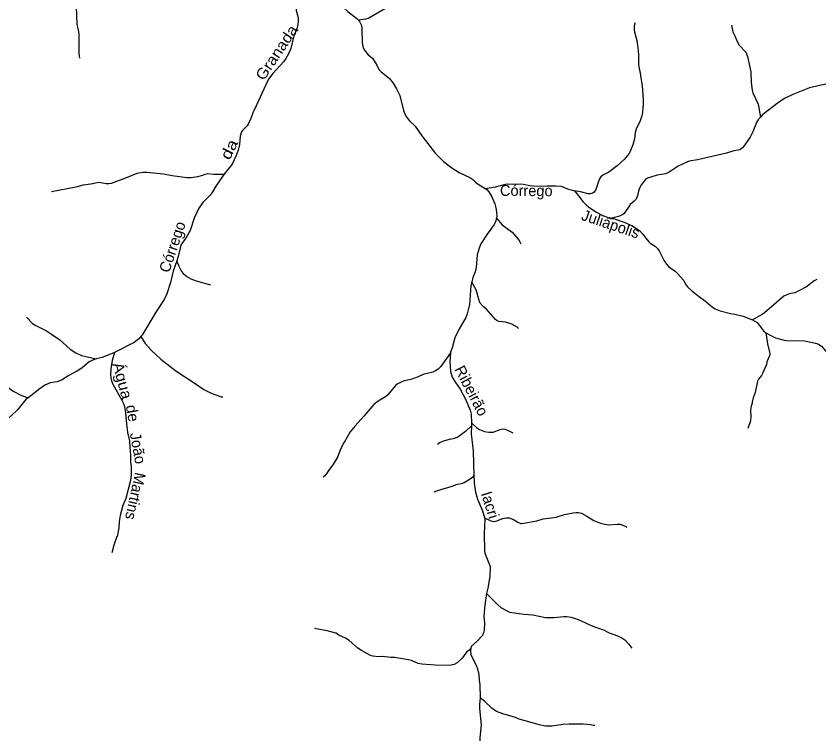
# Model space of a CAD drawing. Extents: x 551.6 to 577.6, y 7567 to 7594.7.
# Drawn here: x 561.8 to 569.17, y 7573.14 to 7579.74 of the extents above; entities that cross this region are included whole.
import ezdxf
from ezdxf.enums import TextEntityAlignment as Align

# ---------------------------------------------------------------- set-up
doc = ezdxf.new("R2010")
doc.units = 0
doc.header["$LTSCALE"] = 0.04
doc.layers.add('61', color=7, linetype='Continuous')
doc.layers.add('7', color=7, linetype='Continuous', lineweight=25)

msp = doc.modelspace()

# ---------------------------------------------------------------- linework, layer by layer
at = {"layer": '7'}
for points in [[(562.302, 7580.2565), (562.2867, 7580.209), (562.2851, 7580.1704), (562.2883, 7580.1511), (562.2883, 7580.077), (562.2931, 7580.032), (562.3068, 7579.9756), (562.3301, 7579.9048), (562.3494, 7579.8227), (562.3543, 7579.6585), (562.368, 7579.6102), (562.372, 7579.57), (562.3736, 7579.3913), (562.3784, 7579.3503)], [(564.2614, 7580.1319), (564.2761, 7580.0754), (564.2906, 7580.0368), (564.3156, 7579.9957), (564.3486, 7579.9563), (564.3598, 7579.9306), (564.3647, 7579.8919), (564.3647, 7579.8275), (564.3687, 7579.7889), (564.3856, 7579.7229), (564.3872, 7579.6972), (564.3824, 7579.6585), (564.3735, 7579.6199), (564.3462, 7579.5555), (564.3188, 7579.4396), (564.2971, 7579.3881), (564.2729, 7579.3455), (564.2504, 7579.3149), (564.1522, 7579.2094), (564.1144, 7579.1579), (564.0878, 7579.1064), (564.0009, 7578.9117)], [(564.7399, 7579.9589), (564.7518, 7579.9467), (564.7791, 7579.8565), (564.7872, 7579.8356), (564.7993, 7579.8195), (564.8403, 7579.7776), (564.9248, 7579.7156), (564.9404, 7579.6981)], [(565.4278, 7579.9949), (565.3715, 7579.9539), (565.332, 7579.916), (565.2693, 7579.8742), (565.1872, 7579.805), (565.0343, 7579.7165), (565.0053, 7579.7084), (564.9404, 7579.6981)], [(564.9404, 7579.6981), (564.9498, 7579.6875), (564.9667, 7579.6489), (564.9715, 7579.6231), (564.9731, 7579.4911), (564.9828, 7579.4461), (564.994, 7579.4219), (565.0294, 7579.3817), (565.0689, 7579.3495), (565.1091, 7579.2867), (565.1228, 7579.2529), (565.1333, 7579.2392), (565.1437, 7579.2271), (565.2234, 7579.1628), (565.2564, 7579.1209), (565.2878, 7579.0694)], [(567.476, 7579.6786), (567.4696, 7579.6376), (567.4704, 7579.6086), (567.4728, 7579.5893), (567.4929, 7579.5121), (567.5034, 7579.4445), (567.5082, 7579.3833), (567.509, 7579.2932), (567.5114, 7579.2706), (567.5259, 7579.2135), (567.5299, 7579.1692), (567.5428, 7579.0968), (567.5525, 7578.9696), (567.5517, 7578.9109), (567.5485, 7578.9036), (567.546, 7578.8505), (567.5404, 7578.8199), (567.5227, 7578.7636), (567.4905, 7578.7073)], [(568.3645, 7579.6529), (568.3758, 7579.5925), (568.3951, 7579.5539), (568.4144, 7579.504), (568.4345, 7579.4686), (568.4941, 7579.4042), (568.5094, 7579.3656), (568.5392, 7579.2239), (568.5432, 7579.1274), (568.552, 7579.0565), (568.5585, 7579.0308), (568.6076, 7578.9278), (568.6289, 7578.8084)], [(569.3866, 7579.1459), (569.3078, 7579.1241), (569.2402, 7579.1145), (569.0776, 7579.0774), (568.9247, 7579.0171), (568.8571, 7578.9817), (568.7943, 7578.943), (568.651, 7578.832), (568.6289, 7578.8084)], [(565.2878, 7579.0694), (565.3192, 7579.0066), (565.353, 7578.8682), (565.3755, 7578.8167), (565.4085, 7578.7749), (565.4608, 7578.7266), (565.522, 7578.6364), (565.6467, 7578.4755), (565.7184, 7578.4014), (565.7972, 7578.3411), (565.864, 7578.2992), (565.9606, 7578.2533), (565.9904, 7578.234), (566.0145, 7578.2099), (566.0387, 7578.1914), (566.1038, 7578.1528)], [(564.0009, 7578.9117), (563.9703, 7578.8473), (563.9518, 7578.7958), (563.9277, 7578.7443), (563.918, 7578.729), (563.8745, 7578.6863), (563.8657, 7578.6735), (563.8528, 7578.6348), (563.848, 7578.5576), (563.8351, 7578.5061), (563.8174, 7578.4546), (563.7788, 7578.3757), (563.7042, 7578.2823)], [(568.6289, 7578.8084), (568.6124, 7578.7909), (568.5931, 7578.7588), (568.5585, 7578.6735), (568.5335, 7578.6252), (568.4764, 7578.5407)], [(567.4905, 7578.7073), (567.48, 7578.667), (567.4728, 7578.6091), (567.4583, 7578.5543), (567.431, 7578.4867), (567.4237, 7578.4755), (567.377, 7578.4183), (567.3127, 7578.3604), (567.2362, 7578.304), (567.1831, 7578.2743), (567.1638, 7578.2598), (567.1509, 7578.2405), (567.142, 7578.2179), (567.1195, 7578.1423), (567.1042, 7578.1205), (567.0865, 7578.1101), (567.0656, 7578.1052), (567.0463, 7578.1052), (566.9787, 7578.1221), (566.9215, 7578.131)], [(568.4764, 7578.5407), (568.4675, 7578.5286), (568.4458, 7578.5109), (568.4241, 7578.5044), (568.3839, 7578.4988), (568.3163, 7578.4787), (568.0523, 7578.4175), (567.975, 7578.4038), (567.9525, 7578.3958), (567.8736, 7578.3588), (567.7899, 7578.304), (567.7593, 7578.2887), (567.6805, 7578.2759), (567.5935, 7578.2477), (567.575, 7578.234), (567.5356, 7578.1882), (567.5163, 7578.1511)], [(563.7042, 7578.2823), (563.6082, 7578.2815), (563.5518, 7578.2871), (563.5293, 7578.2815), (563.5068, 7578.271), (563.4617, 7578.2598), (563.4054, 7578.2517), (563.3651, 7578.2517), (563.2299, 7578.2694), (563.151, 7578.2847), (562.9965, 7578.3), (562.9627, 7578.3), (562.9064, 7578.292), (562.8018, 7578.2469), (562.6698, 7578.2002)], [(563.7042, 7578.2823), (563.6299, 7578.1729), (563.6001, 7578.1214), (563.5768, 7578.0916), (563.5108, 7578.0232), (563.473, 7577.9717), (563.4327, 7577.8815), (563.3941, 7577.7656), (563.3563, 7577.698), (563.3232, 7577.6578), (563.3088, 7577.632), (563.3023, 7577.6063)], [(562.6698, 7578.2002), (562.6472, 7578.1962), (562.6247, 7578.197), (562.5571, 7578.2067), (562.4831, 7578.1922), (562.4139, 7578.1849), (562.3462, 7578.164), (562.1233, 7578.1214)], [(566.1038, 7578.1528), (566.198, 7578.1672), (566.2882, 7578.1938), (566.3107, 7578.197), (566.4008, 7578.193), (566.4234, 7578.1954), (566.4556, 7578.1922), (566.5135, 7578.1793), (566.5779, 7578.1729), (566.668, 7578.1777), (566.7517, 7578.1777), (566.8, 7578.1737), (566.858, 7578.1503), (566.9215, 7578.131)], [(566.1038, 7578.1528), (566.1175, 7578.1447), (566.1368, 7578.123), (566.1642, 7578.0763), (566.19, 7578.0119), (566.1972, 7577.9862)], [(566.9215, 7578.131), (566.9601, 7578.0868), (566.9996, 7578.0344), (567.0286, 7578.0038), (567.0503, 7577.9853), (567.1179, 7577.9395), (567.175, 7577.9073), (567.2539, 7577.8783)], [(567.5163, 7578.1511), (567.505, 7578.1149), (567.5018, 7578.086), (567.4889, 7578.0554), (567.4696, 7578.0352), (567.4334, 7578.0071), (567.431, 7577.999), (567.377, 7577.9242), (567.3561, 7577.9073), (567.3264, 7577.8952), (567.2539, 7577.8783)], [(566.1972, 7577.9862), (566.2044, 7577.9604), (566.2101, 7577.8992), (566.2057, 7577.8815)], [(566.2057, 7577.8815), (566.1972, 7577.8477), (566.1843, 7577.8236), (566.1207, 7577.7335), (566.0636, 7577.6449), (566.0459, 7577.6063), (566.0282, 7577.5451), (566.0201, 7577.426), (566.0105, 7577.3874), (565.9896, 7577.3359), (565.9789, 7577.2913)], [(566.2057, 7577.8815), (566.2568, 7577.8195), (566.3501, 7577.7528), (566.3912, 7577.7061), (566.4129, 7577.6763), (566.4282, 7577.6457)], [(567.2539, 7577.8783), (567.2797, 7577.8759), (567.3795, 7577.8429), (567.4527, 7577.8107), (567.5187, 7577.7664), (567.5436, 7577.7407), (567.5879, 7577.6819), (567.6072, 7577.661), (567.6177, 7577.6513), (567.6636, 7577.624), (567.6853, 7577.6023), (567.6998, 7577.5805), (567.7464, 7577.4888), (567.7674, 7577.4566), (567.7891, 7577.4349), (567.8446, 7577.3938), (567.8672, 7577.3729), (567.9243, 7577.3069), (567.9404, 7577.2731), (567.9581, 7577.249), (568.0008, 7577.2111), (568.0821, 7577.1475), (568.1255, 7577.1194), (568.1674, 7577.0824)], [(563.3023, 7577.6063), (563.2846, 7577.5274), (563.2714, 7577.4883)], [(563.2714, 7577.4883), (563.2396, 7577.3938), (563.2154, 7577.2892), (563.1816, 7577.1862), (563.1575, 7577.1347), (563.0786, 7577.0172), (562.9563, 7576.8112), (562.9409, 7576.7931)], [(563.5832, 7577.2642), (563.452, 7577.3021), (563.4038, 7577.3198), (563.3611, 7577.3447), (563.3385, 7577.364), (563.3136, 7577.3987), (563.2927, 7577.4373), (563.2714, 7577.4883)], [(565.9789, 7577.2913), (565.971, 7577.2586), (565.9574, 7577.0864), (565.9372, 7577.0011), (565.9236, 7576.9673), (565.8616, 7576.8578), (565.8254, 7576.7806)], [(566.4097, 7576.8667), (566.396, 7576.8795), (566.3477, 7576.9061), (566.2897, 7576.9246), (566.227, 7576.9327), (566.2109, 7576.9383), (566.1956, 7576.9504), (566.1127, 7577.0486), (566.0861, 7577.0663), (566.0572, 7577.0993), (566.0467, 7577.1234), (566.0193, 7577.2216), (565.9789, 7577.2913)], [(569.146, 7577.3166), (569.1227, 7577.3037), (569.0502, 7577.2506), (568.981, 7577.2119), (568.9456, 7577.1958), (568.8909, 7577.1846), (568.8426, 7577.1644), (568.6663, 7577.0107), (568.6446, 7576.9954), (568.5552, 7576.9475)], [(561.1141, 7577.092), (561.1294, 7577.0574), (561.1608, 7577.0124), (561.2099, 7576.9222), (561.2348, 7576.8836), (561.296, 7576.8103), (561.3443, 7576.7596), (561.3909, 7576.684), (561.4561, 7576.5914), (561.5511, 7576.4828), (561.6138, 7576.4216), (561.6138, 7576.4176), (561.6646, 7576.3725), (561.77, 7576.2912), (561.8473, 7576.2526), (561.908, 7576.2318)], [(568.1674, 7577.0824), (568.1883, 7577.0638), (568.214, 7577.0477), (568.2583, 7577.0284), (568.3549, 7577.0043), (568.3935, 7576.9995), (568.4692, 7576.9793), (568.5552, 7576.9475)], [(561.894, 7576.9697), (561.9487, 7576.9141), (561.9712, 7576.8989), (562.0774, 7576.8457), (562.1129, 7576.8216), (562.1973, 7576.7636), (562.2923, 7576.6783), (562.3462, 7576.6437), (562.3978, 7576.6196), (562.5332, 7576.5876)], [(568.5552, 7576.9475), (568.5987, 7576.9222), (568.6559, 7576.8466), (568.6786, 7576.8276)], [(562.9409, 7576.7931), (562.9241, 7576.7733), (562.8814, 7576.7395), (562.7003, 7576.6472)], [(562.9409, 7576.7931), (562.982, 7576.7307), (563.0392, 7576.6639), (563.1253, 7576.5858), (563.2621, 7576.4779), (563.4327, 7576.3677), (563.5212, 7576.3057), (563.5808, 7576.2776), (563.6806, 7576.2405), (563.6959, 7576.2381)], [(565.8254, 7576.7806), (565.8004, 7576.6888), (565.7843, 7576.651), (565.7837, 7576.6426)], [(568.6786, 7576.8276), (568.6937, 7576.7258), (568.7122, 7576.6502), (568.7138, 7576.6381), (568.7106, 7576.6164), (568.6881, 7576.5601), (568.6832, 7576.5359), (568.6478, 7576.4538), (568.6374, 7576.4353), (568.6108, 7576.4023), (568.6011, 7576.383), (568.581, 7576.2784), (568.5625, 7576.2301), (568.5528, 7576.1898), (568.5537, 7576.1818), (568.5432, 7576.1528), (568.5384, 7576.1158), (568.54, 7576.0514), (568.5368, 7576.0337)], [(568.6786, 7576.8276), (568.7187, 7576.8047), (568.7669, 7576.7822), (568.8458, 7576.7612), (568.8683, 7576.758), (569.0341, 7576.7548), (569.1355, 7576.7339), (569.1549, 7576.7274), (569.1886, 7576.7049), (569.2506, 7576.6341)], [(562.7003, 7576.6472), (562.5861, 7576.6011), (562.5332, 7576.5876), (562.4911, 7576.5729)], [(562.7003, 7576.6472), (562.6786, 7576.5729), (562.6665, 7576.4957), (562.6641, 7576.4442), (562.6674, 7576.4152), (562.6738, 7576.3862), (562.685, 7576.3556), (562.7679, 7576.2092), (562.7824, 7576.1786), (562.7913, 7576.1496), (562.8017, 7576.0917), (562.8098, 7575.9903), (562.8203, 7575.913), (562.8372, 7575.8357), (562.8404, 7575.7697), (562.8452, 7575.7472), (562.8484, 7575.7021), (562.8484, 7575.6394), (562.8533, 7575.6007)], [(565.7837, 7576.6426), (565.695, 7576.5166), (565.6709, 7576.4948), (565.6475, 7576.4787), (565.6234, 7576.4659), (565.5341, 7576.4441), (565.4866, 7576.4224), (565.419, 7576.3991), (565.3594, 7576.3862), (565.3192, 7576.3693), (565.2934, 7576.3548), (565.2781, 7576.3427), (565.2089, 7576.2591), (565.1888, 7576.2405), (565.1188, 7576.2011), (565.0801, 7576.1681), (564.9884, 7576.0627)], [(565.7837, 7576.6426), (565.7779, 7576.5649), (565.7843, 7576.4731), (565.7996, 7576.4216), (565.8294, 7576.3701), (565.8729, 7576.309), (565.9203, 7576.2188), (565.9646, 7576.1174), (565.9735, 7576.0788), (565.9778, 7575.9994), (565.9755, 7575.9722)], [(562.4911, 7576.5729), (562.4686, 7576.56), (562.3994, 7576.5037), (562.3559, 7576.4739), (562.2819, 7576.4369), (562.2127, 7576.3934), (562.174, 7576.3781), (562.1096, 7576.3685), (562.0597, 7576.346), (562.005, 7576.3081), (561.9712, 7576.2783), (561.908, 7576.2318)], [(561.908, 7576.2318), (561.8835, 7576.2116), (561.8086, 7576.1198), (561.7595, 7576.0699), (561.6995, 7576.0188)], [(564.9884, 7576.0627), (564.9079, 7575.9733), (564.8644, 7575.9194), (564.8073, 7575.8212), (564.8041, 7575.8204), (564.7993, 7575.8035), (564.796, 7575.8027), (564.7703, 7575.7504), (564.7461, 7575.686), (564.7292, 7575.6538), (564.7043, 7575.6152), (564.6722, 7575.5737), (564.6504, 7575.5379), (564.6303, 7575.5138), (564.615, 7575.5009)], [(568.5368, 7576.0337), (568.5368, 7576.02), (568.5134, 7575.9492)], [(565.9755, 7575.9722), (565.9228, 7575.9202), (565.8503, 7575.8703), (565.8101, 7575.8526), (565.7715, 7575.8486), (565.7184, 7575.8317), (565.6894, 7575.8188), (565.6644, 7575.8027)], [(565.9755, 7575.9722), (565.9727, 7575.9001), (565.9912, 7575.7424), (565.996, 7575.6233), (565.9997, 7575.5214)], [(565.9778, 7575.9994), (566.0234, 7575.9589), (566.0499, 7575.9403), (566.095, 7575.9226), (566.1352, 7575.9162), (566.1755, 7575.9154), (566.2399, 7575.9403), (566.264, 7575.946), (566.2857, 7575.9419), (566.3139, 7575.9307), (566.355, 7575.9074)], [(562.8533, 7575.6007), (562.8533, 7575.5283), (562.8476, 7575.472), (562.8034, 7575.3062), (562.7776, 7575.2402), (562.751, 7575.1508), (562.7422, 7575.0953), (562.739, 7575.0374), (562.7261, 7574.9569), (562.7229, 7574.9553), (562.6939, 7574.8764), (562.6746, 7574.8064)], [(565.9997, 7575.5214), (565.9912, 7575.5057), (565.9751, 7575.4904), (565.9083, 7575.4502), (565.8809, 7575.4398), (565.8326, 7575.4301), (565.8005, 7575.4172), (565.7007, 7575.3899), (565.6564, 7575.3746), (565.6322, 7575.3625)], [(565.9997, 7575.5214), (566.0024, 7575.4478), (566.0145, 7575.3641), (566.0322, 7575.2997), (566.0765, 7575.1935), (566.0948, 7575.1269)], [(566.0948, 7575.1269), (566.1529, 7575.0993), (566.1851, 7575.0953), (566.2093, 7575.1001), (566.2656, 7575.1211), (566.2946, 7575.1275), (566.3236, 7575.1291), (566.3638, 7575.113), (566.4008, 7575.0881), (566.4298, 7575.0776), (566.4395, 7575.0776), (566.5763, 7575.1001), (566.6342, 7575.1186), (566.7115, 7575.1275), (566.7533, 7575.1355), (566.8306, 7575.1581), (566.9111, 7575.175), (566.9368, 7575.1774)], [(566.9368, 7575.1774), (566.9561, 7575.1774), (566.9851, 7575.1709), (567.0366, 7575.1436), (567.0986, 7575.1041), (567.1606, 7575.0784), (567.1992, 7575.0695), (567.2378, 7575.0655), (567.3151, 7575.0712), (567.3408, 7575.0687), (567.3811, 7575.0534), (567.4028, 7575.0414)], [(566.0948, 7575.1269), (566.0982, 7575.1146), (566.0942, 7574.9826), (566.095, 7574.8281), (566.0998, 7574.8024), (566.1481, 7574.68), (566.1457, 7574.5883), (566.1264, 7574.4837), (566.116, 7574.4329)], [(566.116, 7574.4329), (566.0982, 7574.3291), (566.091, 7574.2245), (566.095, 7574.1601), (566.0918, 7574.0974), (566.0877, 7574.0732), (566.0781, 7574.0474), (566.0298, 7573.9968), (565.9775, 7573.9493), (565.9715, 7573.9327)], [(566.116, 7574.4329), (566.2173, 7574.3307), (566.2463, 7574.3058), (566.3252, 7574.2631), (566.4604, 7574.2422), (566.5393, 7574.2374), (566.6551, 7574.214), (566.7324, 7574.2116), (566.8258, 7574.2213), (566.8515, 7574.2213), (566.8901, 7574.2148), (566.9545, 7574.1931), (567.0978, 7574.1311), (567.1879, 7574.1006), (567.2394, 7574.0716), (567.3167, 7574.0458)], [(564.9683, 7573.909), (564.9337, 7573.9316), (564.8532, 7574.0024), (564.8138, 7574.0257), (564.7655, 7574.0474), (564.7325, 7574.0676), (564.6528, 7574.0917), (564.5361, 7574.1127)], [(567.3167, 7574.0458), (567.3569, 7574.0249), (567.3827, 7574.0072), (567.4205, 7573.9686), (567.4487, 7573.9308)], [(565.9715, 7573.9327), (565.9542, 7573.913), (565.9324, 7573.8945), (565.8925, 7573.8386), (565.8455, 7573.7972), (565.8165, 7573.7819), (565.7763, 7573.7722), (565.6443, 7573.7754), (565.5204, 7573.7843), (565.4866, 7573.7915), (565.4254, 7573.8181), (565.3981, 7573.8253), (565.2693, 7573.8446), (565.2355, 7573.8454), (565.1614, 7573.8543), (565.1228, 7573.8527), (565.0713, 7573.8591), (565.0512, 7573.8648), (564.9683, 7573.909)], [(565.9715, 7573.9327), (565.967, 7573.9058), (565.971, 7573.872), (566.0234, 7573.7658), (566.0322, 7573.74), (566.0435, 7573.6885), (566.0467, 7573.6386), (566.0539, 7573.5936), (566.0561, 7573.4754)], [(566.0561, 7573.4754), (566.0499, 7573.4133), (566.0515, 7573.3763)], [(567.1099, 7573.2201), (567.093, 7573.2201), (567.0704, 7573.2258), (567.0028, 7573.233), (566.8724, 7573.233), (566.8145, 7573.2298), (566.7163, 7573.2153), (566.6519, 7573.2153), (566.602, 7573.2266), (566.4137, 7573.2797), (566.3799, 7573.2942), (566.264, 7573.328), (566.2061, 7573.3497), (566.1666, 7573.3771), (566.0982, 7573.4422), (566.0561, 7573.4754)], [(566.0515, 7573.3763), (566.066, 7573.2266), (566.0547, 7573.1075), (566.0547, 7573.0716)]]:
    msp.add_lwpolyline(points, dxfattribs=at)

# ---------------------------------------------------------------- texts
at = {"layer": '61'}
for s, rotation, width, p in [('Granada', 56.045, 1.1, (564.2294, 7579.3733)), ('da', 63.435, 1.25, (563.7966, 7578.4901)), ('Água', 285.281, 1.1, (562.7259, 7576.3748)), ('de', 280.338, 1.05, (562.8172, 7576.0802))]:
    msp.add_text(s, height=0.1, rotation=rotation, dxfattribs=dict(at, width=width)).set_placement(p, align=Align.CENTER)
for s, rotation, p in [('Córrego', 359.528, (566.4792, 7578.0838)), ('Juliápolis', 341.411, (567.238, 7577.7794)), ('Córrego', 71.263, (563.2785, 7577.6005)), ('Ribeirão', 297.481, (565.933, 7576.2729)), ('João', 280.338, (562.8665, 7575.7592)), ('Martins', 257.697, (562.8434, 7575.338)), ('Iacri', 287.521, (566.1005, 7575.2316))]:
    msp.add_text(s, height=0.1, rotation=rotation, dxfattribs=at).set_placement(p, align=Align.CENTER)

doc.saveas('drawing.dxf')
